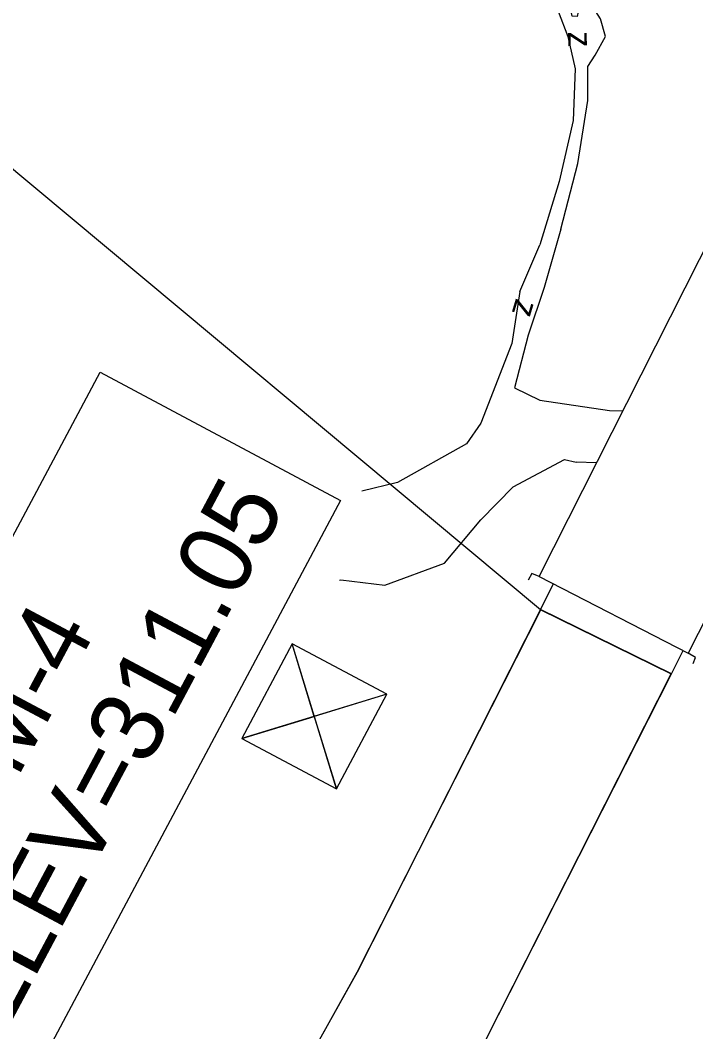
# Model space of a CAD drawing. Extents: x 1970823 to 1988115, y 770601 to 786368.
# Drawn here: x 1977733.7 to 1978012.4, y 782187.9 to 782605.2 of the extents above; entities that cross this region are included whole.
import ezdxf

# ---------------------------------------------------------------- set-up
doc = ezdxf.new("R2010")
doc.units = 0
for name, color, linetype in [('CTL Sheet Text', 7, 'Continuous'), ('CTL Supplemental Horizontal and Vertical Text', 7, 'Continuous'), ('Default', 7, 'Continuous'), ('Old_Level_10', 7, 'Continuous'), ('Old_Level_3', 7, 'Continuous'), ('Old_Level_5', 7, 'Continuous'), ('Old_Level_57', 7, 'Continuous')]:
    doc.layers.add(name, color=color, linetype=linetype)

msp = doc.modelspace()

# ---------------------------------------------------------------- linework, layer by layer
at = {"layer": 'CTL Sheet Text'}
msp.add_line((1977193.91, 782991.61), (1977948.34, 782362.04), dxfattribs=at)
at = {"layer": 'Default'}
for p, q in [((1977872.67, 782212.47), (1977948.46, 782361.98)), ((1977948.46, 782361.98), (1978002.32, 782335.53)), ((1977926.19, 782185.34), (1978002.32, 782335.53)), ((1977823.89, 782125.08), (1977872.67, 782212.47))]:
    msp.add_line(p, q, dxfattribs=at)
msp.add_lwpolyline([(1977634.98, 782212.96), (1977766.59, 782459.94), (1977865.88, 782407.03), (1977734.26, 782160.05)], close=True, dxfattribs=at)
msp.add_lwpolyline([(1977869.36, 782064.37), (1977884.55, 782094.34), (1977926.19, 782185.34), (1978002.39, 782335.5), (1977948.34, 782362.04), (1977872.67, 782212.47), (1977823.89, 782125.08), (1977808.7, 782095.12)], dxfattribs=at)
at = {"layer": 'Old_Level_10'}
for p, q in [((1977956.7, 782519), (1977949.92, 782494.92)), ((1977939.9, 782493.22), (1977948.12, 782512.53)), ((1977923.72, 782438.9), (1977917.78, 782430.4)), ((1977958.31, 782423.9), (1977963.05, 782422.9))]:
    msp.add_line(p, q, dxfattribs=at)
for points in [[(1977956.7, 782519), (1977963.72, 782546.15), (1977967.89, 782572.14), (1977967.86, 782586.12), (1977970.86, 782590.81), (1977975.21, 782598.44), (1977973.15, 782605.71), (1977969.24, 782611.83), (1977970.14, 782617.45), (1977966.33, 782620.34), (1977963.55, 782606.67), (1977961.49, 782606.88), (1977957.88, 782623.82), (1977954.51, 782626.05), (1977955.63, 782608.88), (1977959.63, 782598.42), (1977962.64, 782585.19), (1977961.86, 782563.81), (1977956.06, 782538.64), (1977948.12, 782512.53)], [(1977939.9, 782493.22), (1977936.56, 782471.86), (1977923.72, 782438.9)], [(1977949.92, 782494.92), (1977943.31, 782475.25), (1977937.66, 782453.47), (1977948.09, 782448.38), (1977976.84, 782444.15), (1977982.35, 782444.1)], [(1977917.78, 782430.4), (1977889.33, 782414.45), (1977874.61, 782410.97)], [(1977865.36, 782374.13), (1977865.92, 782374.3), (1977884.16, 782372.13), (1977908.7, 782381.23), (1977923.76, 782399.12), (1977937.02, 782412.73), (1977958.31, 782423.9)], [(1977971.46, 782422.64), (1977963.05, 782422.9)]]:
    msp.add_lwpolyline(points, dxfattribs=at)
at = {"layer": 'Old_Level_3'}
for p, q in [((1977948.34, 782362.04), (1977953.75, 782372.66)), ((1978002.39, 782335.5), (1978007.27, 782345.14))]:
    msp.add_line(p, q, dxfattribs=at)
at = {"layer": 'Old_Level_5'}
for points in [[(1977947.85, 782375.69), (1978026.08, 782530.39)], [(1978088.09, 782499.09), (1978009.24, 782344.12)], [(1977947.85, 782375.69), (1977944.85, 782376.99), (1977943.25, 782374.13)], [(1977947.85, 782375.69), (1978009.24, 782344.12)], [(1978011.38, 782339.86), (1978012.37, 782342.26), (1978009.24, 782344.12)]]:
    msp.add_lwpolyline(points, dxfattribs=at)
at = {"layer": 'Old_Level_57'}
for p, q in [((1977864.12, 782288.09), (1977845.88, 782347.91)), ((1977884.91, 782327.12), (1977825.09, 782308.88))]:
    msp.add_line(p, q, dxfattribs=at)
msp.add_lwpolyline([(1977845.88, 782347.91), (1977825.09, 782308.88), (1977864.12, 782288.09), (1977884.91, 782327.12)], close=True, dxfattribs=at)
for points in [[(1977855, 782318), (1977845.88, 782347.91), (1977825.09, 782308.88), (1977855, 782318)], [(1977855, 782318), (1977864.12, 782288.09), (1977884.91, 782327.12), (1977855, 782318)]]:
    msp.add_lwpolyline(points, dxfattribs=at)

# ---------------------------------------------------------------- texts
at = {"layer": 'CTL Supplemental Horizontal and Vertical Text'}
for s, p in [('ELEV=311.05', (1977726.53, 782185.42)), ('BM-4', (1977719.81, 782268.5))]:
    msp.add_text(s, height=30, rotation=61.9471, dxfattribs=at).set_placement(p)
at = {"layer": 'Old_Level_10'}
for rotation, p in [(271.1928, (1977959.72, 782600.51)), (253.3082, (1977938.32, 782490.79))]:
    msp.add_text('z', height=10, rotation=rotation, dxfattribs=at).set_placement(p)

doc.saveas('drawing.dxf')
